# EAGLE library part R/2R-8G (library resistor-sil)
R/2R Ladder 8 Murata RGSD16L
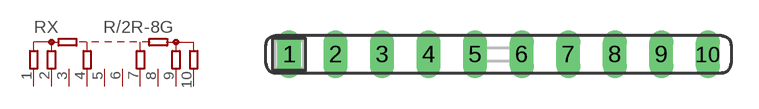
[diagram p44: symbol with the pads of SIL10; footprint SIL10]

Designator prefix RX

## R/2R-8G (OC_FARNELL: unknown; OC_NEWARK: unknown)  [SIL10]
1  IN  pas
2  B8  pas
3  B7  pas
4  B6  pas
5  B5  pas
6  B4  pas
7  B3  pas
8  B2  pas
9  B1  pas
10  OUT  pas

## Footprint SIL10 (pad centres in mm)
Single In Line
drill 0.813 long: 1 -11.43,0; 2 -8.89,0; 3 -6.35,0; 4 -3.81,0; 5 -1.27,0; 6 1.27,0; 7 3.81,0; 8 6.35,0; 9 8.89,0; 10 11.43,0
